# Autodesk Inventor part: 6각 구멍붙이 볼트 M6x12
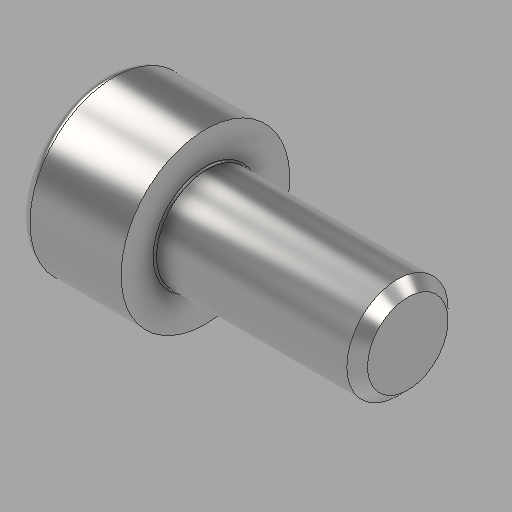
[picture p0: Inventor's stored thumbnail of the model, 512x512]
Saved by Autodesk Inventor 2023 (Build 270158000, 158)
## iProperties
Created: 2025-09
Part Number: 6각 구멍붙이 볼트 M6x12
Material: 강철, 연강
Description: 6각머리 태핑 나사
Document SubType Name: Modeling
Designer: home
Density: 7.85 g/cm^3
Appearance: 기본값
Author: jhkim
Sending System: Autodesk Inventor 2026
Preprocessor: ST-DEVELOPER v20.1
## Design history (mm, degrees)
feature "Solid1"
node "솔리드1"
